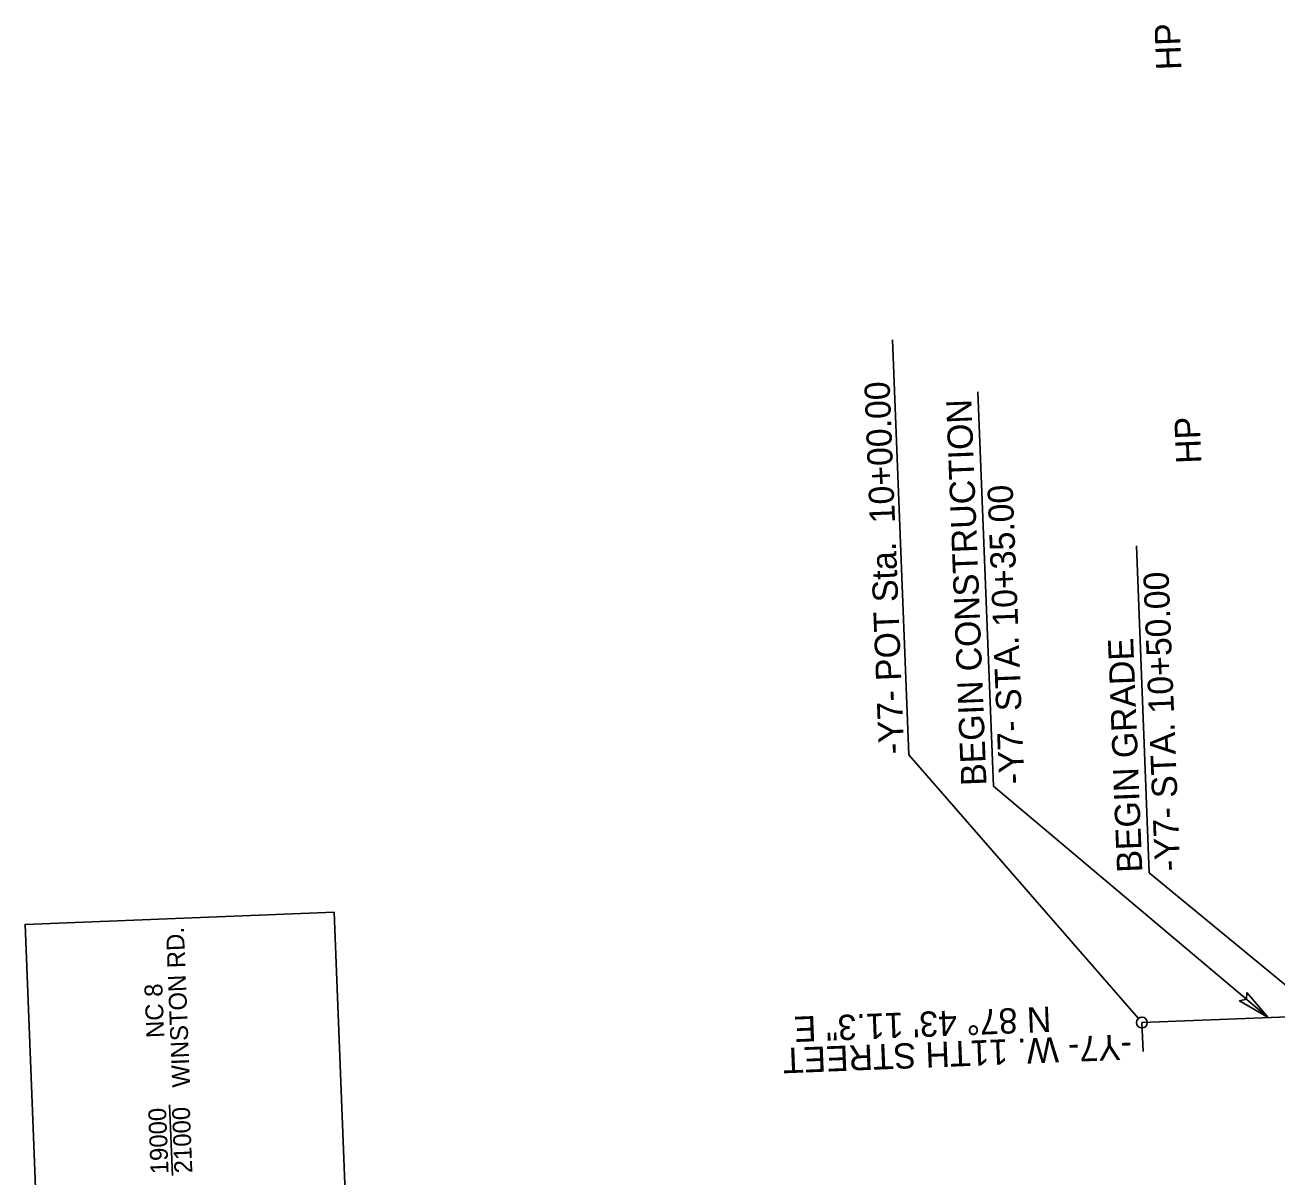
# Model space of a CAD drawing. Extents: x 1627861 to 1629601, y 761281 to 766239.
# Drawn here: x 1627959.5 to 1628306.1, y 763149.5 to 763468.5 of the extents above; entities that cross this region are included whole.
import ezdxf

# ---------------------------------------------------------------- set-up
doc = ezdxf.new("R2010")
doc.units = 0
for name, color, linetype in [('Cogo Default Point CELL', 7, 'Continuous'), ('Default', 7, 'Continuous'), ('Exist Other Culture Sign Leader', 7, 'Continuous'), ('Exist Right of Way Line Leader', 7, 'Continuous'), ('Exist Utilities Gas Meter CELL', 7, 'Continuous'), ('Exist Utilities Gas Meter Cogo Number', 7, 'Continuous'), ('Exist Utilities Water Meter Cogo Elevation', 7, 'Continuous'), ('Scratch_Level_0', 7, 'Continuous')]:
    doc.layers.add(name, color=color, linetype=linetype)

msp = doc.modelspace()

# ---------------------------------------------------------------- linework, layer by layer
at = {"layer": 'Default'}
msp.add_line((1628000.26, 763149.93), (1627999.49, 763169.46), dxfattribs=at)
msp.add_lwpolyline([(1627967.61, 763012.46), (1627959.45, 763219.4), (1628045, 763222.77), (1628053.16, 763015.84)], close=True, dxfattribs=at)
at = {"layer": 'Exist Right of Way Line Leader'}
for p, q in [((1628204.18, 763266.35), (1628199.65, 763381.26)), ((1628267.74, 763193.38), (1628204.18, 763266.35))]:
    msp.add_line(p, q, dxfattribs=at)
msp.add_circle((1628268.7, 763192.24), 1.5, dxfattribs=at)
at = {"layer": 'Exist Utilities Gas Meter CELL'}
msp.add_line((1628268.7, 763192.24), (1628442.96, 763199.17), dxfattribs=at)
msp.add_line((1628268.7, 763192.24), (1628442.96, 763199.17), dxfattribs=at)
at = {"layer": 'Exist Utilities Gas Meter Cogo Number'}
msp.add_lwpolyline([(1628297.79, 763200.61), (1628303.68, 763193.63), (1628295.72, 763198.24), (1628297.63, 763198.72)], close=True, dxfattribs=at)
at = {"layer": 'Exist Utilities Water Meter Cogo Elevation'}
msp.add_line((1628268.7, 763192.24), (1628269.02, 763184.24), dxfattribs=at)
at = {"layer": 'Scratch_Level_0'}
for p, q in [((1628223.29, 763366.91), (1628227.59, 763257.74)), ((1628267.18, 763324.25), (1628270.75, 763233.69)), ((1628303.68, 763193.63), (1628227.59, 763257.74)), ((1628318.66, 763194.23), (1628270.75, 763233.69))]:
    msp.add_line(p, q, dxfattribs=at)

# ---------------------------------------------------------------- texts
at = {"layer": 'Cogo Default Point CELL'}
msp.add_text('N 87%%d 43\' 11.3" E', height=7, rotation=182.2802, dxfattribs=at).set_placement((1628243.44, 763196.67))
at = {"layer": 'Default'}
for s, height, p in [('WINSTON RD.', 4.9438, (1628005.16, 763174.38)), ('NC 8', 4.944, (1627998.02, 763188.08)), ('19000', 4.944, (1627999.2, 763150.35)), ('21000', 4.944, (1628005.79, 763150.61))]:
    msp.add_text(s, height=height, rotation=92.2582, dxfattribs=at).set_placement(p)
at = {"layer": 'Exist Other Culture Sign Leader'}
for s, rotation, p in [('HP', 92.2582, (1628279.68, 763456.11)), ('BEGIN CONSTRUCTION', 92.2582, (1628225.68, 763257.93)), ('HP', 92.2582, (1628285.17, 763347.12)), ('-Y7- STA. 10+35.00', 92.2582, (1628236.17, 763258.35)), ('-Y7- STA. 10+50.00', 92.2582, (1628279.33, 763234.3)), ('BEGIN GRADE', 92.2582, (1628268.83, 763233.89)), ('-Y7- W. 11TH STREET', 182.2802, (1628265.8, 763189.02))]:
    msp.add_text(s, height=7, rotation=rotation, dxfattribs=at).set_placement(p)
at = {"layer": 'Exist Right of Way Line Leader'}
msp.add_text('-Y7- POT Sta.  10+00.00', height=7, rotation=92.2582, dxfattribs=at).set_placement((1628202.89, 763266.7))

doc.saveas('drawing.dxf')
